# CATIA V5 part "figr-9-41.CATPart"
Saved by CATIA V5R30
Part number: Part1
Bounding box of the stored display mesh (mm): x -40 to 40, y -20.616 to 191.034, z 0 to 131.022
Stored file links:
  D:\PROJECTS\CATIA V56R 2020\Resources\Parts File\c09_catia_v5_6r2020_prt\figr-9-41.CATPart
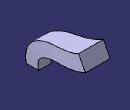
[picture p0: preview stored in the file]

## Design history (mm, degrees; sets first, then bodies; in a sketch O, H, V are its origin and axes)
Set1
  Plane1: type Normal, Curve Sketch2, RefPoint vertex of Sketch2
Body1 (main body)
  Sketch1 on xy-plane, origin (0, 0, 0), H (1, 0, 0), V (0, 1, 0)
    line L1 (20, 20) -> (20, -20)
    line L2 (20, -20) -> (-20, -20)
    line L3 (-20, -20) -> (-20, 20)
    line L4 (-20, 20) -> (20, 20)
    vertical: L1 V, L3 V
    horizontal: L2 H, L4 H
    equidistance: L1 L3 O, L2 L4 O
  Sketch2 on yz-plane, origin (0, 0, 0), H (0, 1, 0), V (0, 0, 1)
    spline S1 through (0, 0) (20, 60) (60, 80) (120, 90) (180, 110)
    point P1 (0, 0)
    coincidence: P1 O
  Sketch3 on Plane1, origin (0, 186.3865, 97.8327), H (1, 0, 0), V (0, -0.4648, 0.8854)
    point P1 (0, 13.7415)
    line L1 (40, 37.4831) -> (40, -10)
    line L2 (40, -10) -> (-40, -10)
    line L3 (-40, -10) -> (-40, 37.4831)
    line L4 (-40, 37.4831) -> (40, 37.4831)
    reference projected point E1 (0, 13.7415) from vertex of Sketch2
    coincidence: P1 V, P1 E1
    vertical: L1 V, L3 V
    horizontal: L2 H, L4 H
    equidistance: L1 L3 P1, L2 L4 P1
  Loft1: Sections (Sketch1; Sketch3), Spine Sketch2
